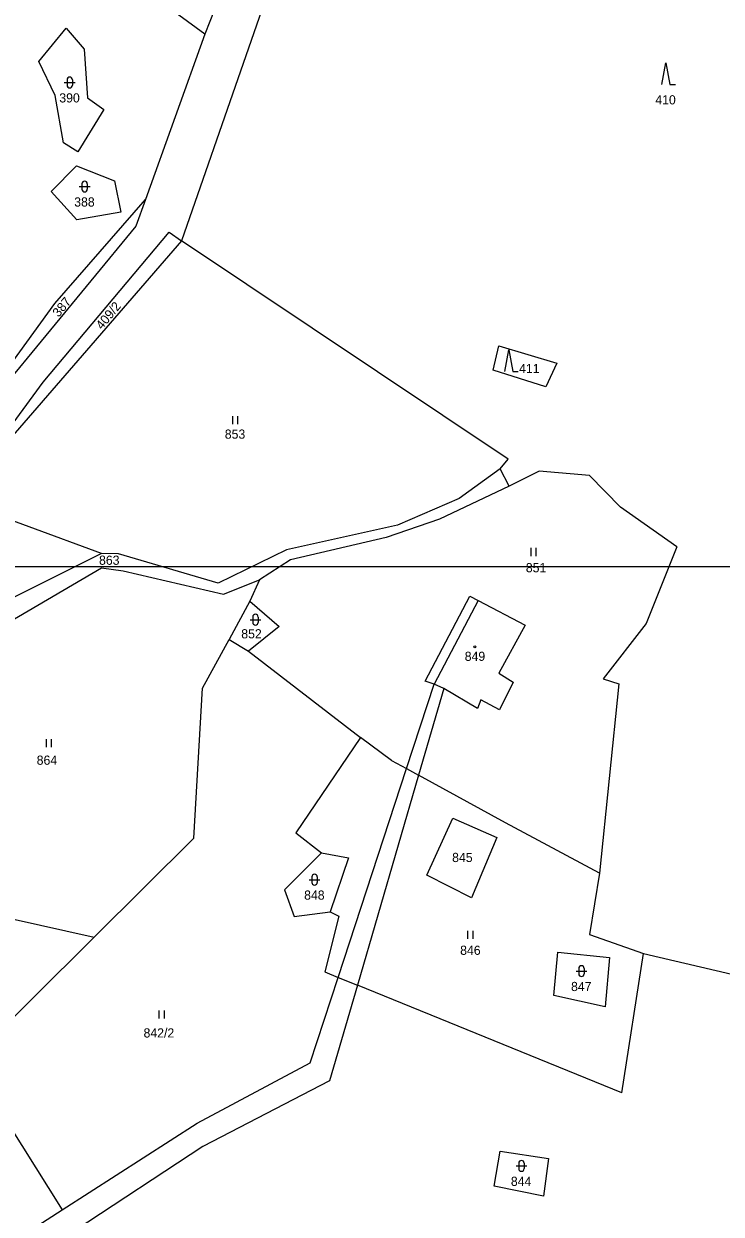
# Model space of a CAD drawing. Extents: x -670359 to -660124, y -978807 to -970072.
# Drawn here: x -669137.4 to -669008.2, y -977619.9 to -977399.4 of the extents above; entities that cross this region are included whole.
import ezdxf

# ---------------------------------------------------------------- set-up
doc = ezdxf.new("R2010")
doc.units = 0
for name, color, linetype in [('Hranice parcel', 7, 'Continuous'), ('ML1000', 7, 'Continuous'), ('Parcelní čísla', 7, 'Continuous'), ('Vnitřní kresba', 7, 'Continuous'), ('Značky budov', 7, 'Continuous'), ('Značky kultur', 7, 'Continuous')]:
    doc.layers.add(name, color=color, linetype=linetype)

msp = doc.modelspace()

# ---------------------------------------------------------------- linework, layer by layer
at = {"layer": 'Hranice parcel'}
for points in [[(-669085.36, -977373.91), (-669108.16, -977439.61)], [(-669092.73, -977373.17), (-669103.87, -977401.38)], [(-669103.87, -977401.38), (-669135.98, -977377.85)], [(-669134.63, -977406.42), (-669129.57, -977400.27)], [(-669129.57, -977400.27), (-669126.22, -977404.12)], [(-669103.87, -977401.38), (-669114.86, -977431.99)], [(-669126.22, -977404.12), (-669125.61, -977413.16)], [(-669131.61, -977412.75), (-669134.63, -977406.42)], [(-669130.04, -977421.47), (-669131.61, -977412.75)], [(-669125.61, -977413.16), (-669122.57, -977415.33)], [(-669122.57, -977415.33), (-669127.4, -977423.16)], [(-669127.4, -977423.16), (-669130.04, -977421.47)], [(-669132.31, -977430.51), (-669127.65, -977425.72)], [(-669127.65, -977425.72), (-669120.62, -977428.54)], [(-669120.62, -977428.54), (-669119.43, -977434.3)], [(-669127.61, -977435.72), (-669132.31, -977430.51)], [(-669131.66, -977451.23), (-669114.86, -977431.99)], [(-669114.86, -977431.99), (-669116.64, -977436.95)], [(-669119.43, -977434.3), (-669127.61, -977435.72)], [(-669116.64, -977436.95), (-669141.64, -977467.28)], [(-669133.84, -977465.83), (-669110.5, -977438.04)], [(-669110.5, -977438.04), (-669108.16, -977439.61)], [(-669108.16, -977439.61), (-669149.88, -977487.66)], [(-669047.69, -977480.11), (-669108.16, -977439.61)], [(-669142.12, -977465.6), (-669131.66, -977451.23)], [(-669050.44, -977463.62), (-669049.38, -977459.06)], [(-669049.38, -977459.06), (-669038.66, -977462.29)], [(-669038.66, -977462.29), (-669040.68, -977466.68)], [(-669040.68, -977466.68), (-669050.44, -977463.62)], [(-669149.88, -977487.66), (-669133.84, -977465.83)], [(-669049.14, -977481.86), (-669047.69, -977480.11)], [(-669049.14, -977481.86), (-669056.76, -977487.36)], [(-669047.46, -977485.07), (-669049.14, -977481.86)], [(-669041.93, -977482.28), (-669047.46, -977485.07)], [(-669032.57, -977483.11), (-669041.93, -977482.28)], [(-669026.82, -977488.96), (-669032.57, -977483.11)], [(-669047.46, -977485.07), (-669060.38, -977491.19)], [(-669056.76, -977487.36), (-669068.15, -977492.29)], [(-669123.01, -977497.58), (-669149.88, -977487.66)], [(-669016.44, -977496.35), (-669026.82, -977488.96)], [(-669060.38, -977491.19), (-669070.24, -977494.6)], [(-669068.15, -977492.29), (-669088.74, -977496.87)], [(-669070.24, -977494.6), (-669088.02, -977498.72)], [(-669123.01, -977497.58), (-669144.82, -977508.4)], [(-669119.89, -977497.59), (-669123.01, -977497.58)], [(-669101.41, -977503.08), (-669119.89, -977497.59)], [(-669088.74, -977496.87), (-669101.41, -977503.08)], [(-669016.44, -977496.35), (-669022.09, -977510.5)], [(-669140.19, -977510.25), (-669123.02, -977500.22)], [(-669123.02, -977500.22), (-669119.02, -977500.79)], [(-669088.02, -977498.72), (-669093.72, -977502.46)], [(-669119.02, -977500.79), (-669100.38, -977505.08)], [(-669100.38, -977505.08), (-669093.72, -977502.46)], [(-669093.72, -977502.46), (-669095.5, -977506.38)], [(-669095.5, -977506.38), (-669099.36, -977513.49)], [(-669095.5, -977506.38), (-669090.07, -977511.11)], [(-669063.04, -977521.19), (-669054.74, -977505.45)], [(-669054.74, -977505.45), (-669053.22, -977506.25)], [(-669053.22, -977506.25), (-669044.51, -977510.84)], [(-669090.07, -977511.11), (-669095.77, -977515.66)], [(-669044.51, -977510.84), (-669049.42, -977519.7)], [(-669022.09, -977510.5), (-669030.05, -977520.8)], [(-669104.28, -977522.51), (-669099.36, -977513.49)], [(-669099.36, -977513.49), (-669095.77, -977515.66)], [(-669095.77, -977515.66), (-669075, -977531.63)], [(-669049.42, -977519.7), (-669046.71, -977521.39)], [(-669105.89, -977550.27), (-669104.28, -977522.51)], [(-669061.36, -977521.75), (-669063.04, -977521.19)], [(-669059.6, -977522.56), (-669061.36, -977521.75)], [(-669053.37, -977526.25), (-669059.6, -977522.56)], [(-669046.71, -977521.39), (-669049.29, -977526.51)], [(-669027.17, -977521.69), (-669030.73, -977556.8)], [(-669030.05, -977520.8), (-669027.17, -977521.69)], [(-669052.72, -977524.66), (-669053.37, -977526.25)], [(-669049.29, -977526.51), (-669052.72, -977524.66)], [(-669075, -977531.63), (-669086.99, -977549.28)], [(-669069.25, -977535.89), (-669075, -977531.63)], [(-669069.25, -977535.89), (-669066.49, -977537.41)], [(-669066.49, -977537.41), (-669064.27, -977538.62)], [(-669048.15, -977547.47), (-669064.27, -977538.62)], [(-669062.76, -977557.11), (-669057.92, -977546.56)], [(-669057.92, -977546.56), (-669049.77, -977550.19)], [(-669030.73, -977556.8), (-669048.15, -977547.47)], [(-669105.89, -977550.27), (-669124.36, -977568.61)], [(-669086.99, -977549.28), (-669082.28, -977552.98)], [(-669049.77, -977550.19), (-669054.45, -977561.37)], [(-669082.28, -977552.98), (-669089.11, -977559.84)], [(-669082.28, -977552.98), (-669077.24, -977553.95)], [(-669077.24, -977553.95), (-669080.64, -977563.94)], [(-669054.45, -977561.37), (-669062.76, -977557.11)], [(-669030.73, -977556.8), (-669032.61, -977568.16)], [(-669169.48, -977558.58), (-669124.36, -977568.61)], [(-669089.11, -977559.84), (-669087.29, -977564.8)], [(-669087.29, -977564.8), (-669080.64, -977563.94)], [(-669080.64, -977563.94), (-669079.04, -977564.75)], [(-669079.04, -977564.75), (-669081.63, -977575.06)], [(-669147.59, -977591.68), (-669124.36, -977568.61)], [(-669032.61, -977568.16), (-669022.61, -977571.62)], [(-669039.21, -977579.42), (-669038.47, -977571.42)], [(-669038.47, -977571.42), (-669028.86, -977572.41)], [(-669028.86, -977572.41), (-669029.69, -977581.52)], [(-669026.62, -977597.45), (-669022.61, -977571.62)], [(-669022.61, -977571.62), (-668988.01, -977579.77)], [(-669081.63, -977575.06), (-669079.14, -977576.08)], [(-669084.33, -977591.93), (-669079.14, -977576.08)], [(-669075.59, -977577.52), (-669080.74, -977595.22)], [(-669079.14, -977576.08), (-669075.59, -977577.52)], [(-669026.62, -977597.45), (-669075.59, -977577.52)], [(-669029.69, -977581.52), (-669039.21, -977579.42)], [(-669147.59, -977591.68), (-669130.3, -977619.14)], [(-669105.27, -977603.08), (-669084.33, -977591.93)], [(-669080.74, -977595.22), (-669104.24, -977607.4)], [(-669130.3, -977619.14), (-669105.27, -977603.08)], [(-669104.24, -977607.4), (-669127.9, -977622.95)], [(-669050.27, -977614.72), (-669049.12, -977608.24)], [(-669049.12, -977608.24), (-669040.16, -977609.63)], [(-669040.16, -977609.63), (-669041.14, -977616.59)], [(-669041.14, -977616.59), (-669050.27, -977614.72)], [(-669156.04, -977635.66), (-669130.3, -977619.14)]]:
    msp.add_lwpolyline(points, dxfattribs=at)
at = {"layer": 'ML1000'}
msp.add_lwpolyline([(-668750, -977000), (-668750, -977500), (-669375, -977500), (-669375, -977000)], close=True, dxfattribs=at)
at = {"layer": 'Vnitřní kresba'}
for points in [[(-669053.22, -977506.25), (-669061.36, -977521.75)], [(-669066.49, -977537.41), (-669061.36, -977521.75)], [(-669059.6, -977522.56), (-669064.27, -977538.62)], [(-669079.14, -977576.08), (-669066.49, -977537.41)], [(-669064.27, -977538.62), (-669075.59, -977577.52)]]:
    msp.add_lwpolyline(points, dxfattribs=at)
at = {"layer": 'Značky budov'}
msp.add_circle((-669053.82, -977514.85), 0.175, dxfattribs=at)
at = {"layer": 'Značky kultur'}
for p, q in [((-669129.9, -977410.31), (-669127.9, -977410.31)), ((-669129.4, -977409.81), (-669129.4, -977410.81)), ((-669128.4, -977409.81), (-669128.4, -977410.81)), ((-669127.14, -977429.59), (-669125.14, -977429.59)), ((-669126.64, -977429.09), (-669126.64, -977430.09)), ((-669125.64, -977429.09), (-669125.64, -977430.09)), ((-669098.74, -977472.09), (-669098.74, -977473.59)), ((-669097.74, -977473.59), (-669097.74, -977472.09)), ((-669043.47, -977496.53), (-669043.47, -977498.03)), ((-669042.47, -977498.03), (-669042.47, -977496.53)), ((-669094.99, -977509.32), (-669094.99, -977510.32)), ((-669093.99, -977509.32), (-669093.99, -977510.32)), ((-669095.49, -977509.82), (-669093.49, -977509.82)), ((-669133.25, -977531.96), (-669133.25, -977533.46)), ((-669132.25, -977533.46), (-669132.25, -977531.96)), ((-669084.54, -977557.98), (-669082.54, -977557.98)), ((-669084.04, -977557.48), (-669084.04, -977558.48)), ((-669083.04, -977557.48), (-669083.04, -977558.48)), ((-669055.17, -977567.46), (-669055.17, -977568.96)), ((-669054.17, -977568.96), (-669054.17, -977567.46)), ((-669035.08, -977574.91), (-669033.08, -977574.91)), ((-669034.58, -977574.41), (-669034.58, -977575.41)), ((-669033.58, -977574.41), (-669033.58, -977575.41)), ((-669112.37, -977582.2), (-669112.37, -977583.7)), ((-669111.37, -977583.7), (-669111.37, -977582.2)), ((-669046.2, -977611), (-669044.2, -977611)), ((-669045.7, -977610.5), (-669045.7, -977611.5)), ((-669044.7, -977610.5), (-669044.7, -977611.5))]:
    msp.add_line(p, q, dxfattribs=at)
for points in [[(-669019.18, -977410.69), (-669018.43, -977406.69), (-669017.68, -977410.69), (-669016.68, -977410.69)], [(-669048.29, -977463.85), (-669047.54, -977459.85), (-669046.79, -977463.85), (-669045.79, -977463.85)]]:
    msp.add_lwpolyline(points, dxfattribs=at)
msp.add_circle((-669053.82, -977514.85), 0.175, dxfattribs=at)
for centre, start, end in [((-669128.9, -977409.81), 0, 180), ((-669128.9, -977410.81), 180, 0), ((-669126.14, -977429.09), 0, 180), ((-669126.14, -977430.09), 180, 0), ((-669094.49, -977509.32), 0, 180), ((-669094.49, -977510.32), 180, 0), ((-669083.54, -977557.48), 0, 180), ((-669083.54, -977558.48), 180, 0), ((-669034.08, -977574.41), 0, 180), ((-669034.08, -977575.41), 180, 0), ((-669045.2, -977610.5), 0, 180), ((-669045.2, -977611.5), 180, 0)]:
    msp.add_arc(centre, 0.5, start, end, dxfattribs=at)

# ---------------------------------------------------------------- texts
at = {"layer": 'Parcelní čísla'}
for s, p in [('390', (-669130.83, -977414.01)), ('410', (-669020.4, -977414.37)), ('388', (-669128.07, -977433.29)), ('411', (-669045.64, -977464.14)), ('853', (-669100.17, -977476.29)), ('863', (-669123.47, -977499.65)), ('851', (-669044.39, -977501.03)), ('852', (-669097.12, -977513.28)), ('849', (-669055.71, -977517.45)), ('864', (-669135.02, -977536.69)), ('845', (-669058.05, -977554.71)), ('848', (-669085.47, -977561.68)), ('846', (-669056.56, -977571.9)), ('847', (-669036.01, -977578.61)), ('842/2', (-669115.22, -977587.21)), ('844', (-669047.16, -977614.7))]:
    msp.add_text(s, height=1.7, dxfattribs=at).set_placement(p)
for s, rotation, p in [('387', 49.9166, (-669130.96, -977453.89)), ('409/2', 50.4613, (-669122.92, -977456.2))]:
    msp.add_text(s, height=1.7, rotation=rotation, dxfattribs=at).set_placement(p)

doc.saveas('drawing.dxf')
